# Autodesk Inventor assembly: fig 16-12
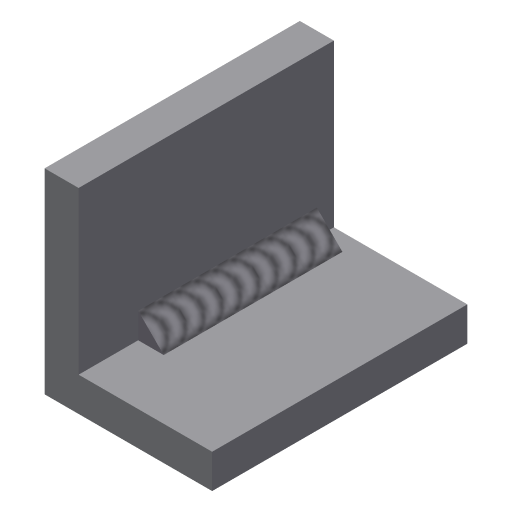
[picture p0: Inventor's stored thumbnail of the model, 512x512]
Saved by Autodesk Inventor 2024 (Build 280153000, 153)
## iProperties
Created: 2009-05
Part Number: fig 16-12
Document SubType Name: Weldment
Designer: Sham
Weld Material: Welded Aluminum-6061
Author: Sham
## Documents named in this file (2)
- D:\PROJECTS\Project 2023\RESOURCES INVENTOR 2024\RESOURCES INVENTOR 2024\Inventor_2023_Part\Inventor_2024_Part\c16_Inv_2024_prt\fig 16-12.iam
- D:\PROJECTS\Project 2023\RESOURCES INVENTOR 2024\RESOURCES INVENTOR 2024\Inventor_2023_Part\Inventor_2024_Part\c16_Inv_2024_prt\Part3.ipt
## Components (1 placed, 1 different names)
1. Part3:1
